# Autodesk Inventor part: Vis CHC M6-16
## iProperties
Shininess: 20.0
Angle Display Precision: 2
Document Length Units: 11269
Document Angle Units: 11279
Document Time Units: 11290
Document Mass Units: 11283
Document Length Units Precision: 3
Document Angle Units Precision: 2
Compacted: True
Created: 2002-04
Part Number: Vis CHC M6-16
Material: Par défaut
Document SubType Name: Modélisation
Designer: thchene
Density: 0.0
Volumn: 0.0
Area: 0.0
PropertySet Name: Model Information
Control State: 0
Master: False
Checked Out: False
Author: thchene
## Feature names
1. Révolution1 [Revolution]
2. Chanfrein1 [Chamfer]
3. Congé1 [Fillet]
4. Extrusion1
5. Extrusion3
